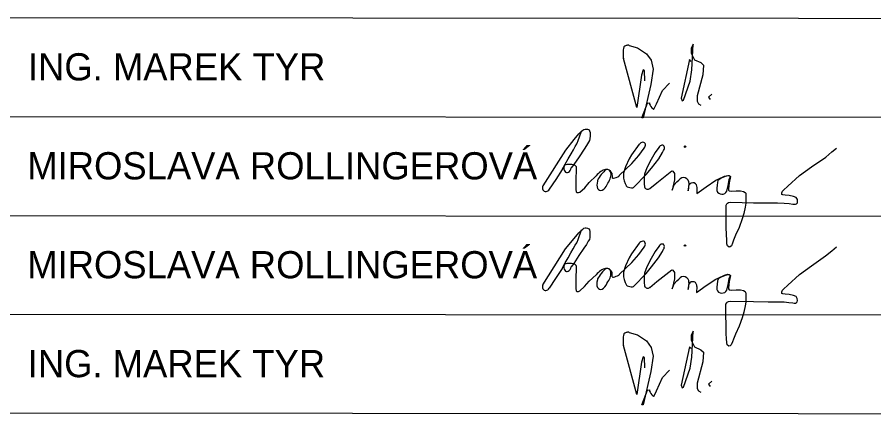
# Model space of a CAD drawing. Extents: x -467927 to -455912, y -1105662 to -1104439.
# Drawn here: x -458189.3 to -458127.1, y -1105019.6 to -1104991.1 of the extents above; entities that cross this region are included whole.
import ezdxf

# ---------------------------------------------------------------- set-up
doc = ezdxf.new("R2010")
doc.units = 0
doc.layers.add('Implicitní', color=7, linetype='Continuous')
doc.layers.add('Rozpiska TMS', color=7, linetype='Continuous')

msp = doc.modelspace()

# ---------------------------------------------------------------- linework, layer by layer
at = {"layer": 'Implicitní'}
for p, q in [((-458229.752, -1104998.32), (-458124.713, -1104998.397)), ((-458148.843, -1105000.022), (-458148.494, -1104999.613)), ((-458148.567, -1105000.17), (-458148.302, -1104999.411)), ((-458148.494, -1104999.613), (-458148.302, -1104999.418)), ((-458148.302, -1104999.418), (-458148.216, -1104999.346)), ((-458148.216, -1104999.346), (-458148.145, -1104999.292)), ((-458148.145, -1104999.292), (-458148.049, -1104999.267)), ((-458148.049, -1104999.267), (-458147.969, -1104999.267)), ((-458147.969, -1104999.267), (-458147.874, -1104999.285)), ((-458147.874, -1104999.285), (-458147.809, -1104999.308)), ((-458147.809, -1104999.308), (-458147.753, -1104999.332)), ((-458147.753, -1104999.332), (-458147.719, -1104999.406)), ((-458147.719, -1104999.406), (-458147.689, -1104999.517)), ((-458147.689, -1104999.517), (-458147.689, -1104999.755)), ((-458149.455, -1105000.795), (-458148.843, -1105000.022)), ((-458147.811, -1105000.225), (-458147.945, -1105000.46)), ((-458147.724, -1105000.094), (-458147.811, -1105000.225)), ((-458147.706, -1104999.97), (-458147.724, -1105000.094)), ((-458147.689, -1104999.755), (-458147.706, -1104999.97)), ((-458151.108, -1105003.4), (-458149.455, -1105000.795)), ((-458148.126, -1105000.735), (-458148.487, -1105001.277)), ((-458147.945, -1105000.46), (-458148.126, -1105000.735)), ((-458144.11, -1105000.376), (-458144.676, -1105001.138)), ((-458144.132, -1105001.198), (-458143.74, -1105000.665)), ((-458142.683, -1105000.613), (-458142.951, -1105000.973)), ((-458142.424, -1105000.969), (-458142.344, -1105000.817)), ((-458130.553, -1105001.306), (-458130.099, -1105000.92)), ((-458130.099, -1105000.92), (-458129.758, -1105000.648)), ((-458148.487, -1105001.277), (-458148.869, -1105001.852)), ((-458144.844, -1105001.435), (-458145.109, -1105002.013)), ((-458144.676, -1105001.138), (-458144.844, -1105001.435)), ((-458144.649, -1105001.775), (-458144.132, -1105001.198)), ((-458143.245, -1105001.485), (-458143.552, -1105002.083)), ((-458142.951, -1105000.973), (-458143.245, -1105001.485)), ((-458143.225, -1105002.104), (-458142.697, -1105001.429)), ((-458142.697, -1105001.429), (-458142.424, -1105000.969)), ((-458131.585, -1105002.01), (-458130.553, -1105001.306)), ((-458148.869, -1105001.852), (-458149.049, -1105002.086)), ((-458148.696, -1105001.998), (-458148.713, -1105003.148)), ((-458145.537, -1105002.62), (-458144.649, -1105001.775)), ((-458145.109, -1105002.013), (-458145.243, -1105002.476)), ((-458143.552, -1105002.083), (-458143.72, -1105002.551)), ((-458143.596, -1105002.581), (-458143.225, -1105002.104)), ((-458132.459, -1105002.646), (-458131.585, -1105002.01)), ((-458149.717, -1105002.221), (-458150.185, -1105002.945)), ((-458147.74, -1105003.147), (-458147.239, -1105002.677)), ((-458145.243, -1105002.476), (-458145.261, -1105002.649)), ((-458145.261, -1105002.649), (-458145.261, -1105002.834)), ((-458144.497, -1105003.49), (-458143.596, -1105002.581)), ((-458143.72, -1105002.551), (-458143.75, -1105002.738)), ((-458143.75, -1105002.738), (-458143.75, -1105003.222)), ((-458142.834, -1105003.169), (-458141.74, -1105002.303)), ((-458141.74, -1105002.303), (-458141.656, -1105002.327)), ((-458141.656, -1105002.327), (-458141.547, -1105002.496)), ((-458141.547, -1105002.496), (-458141.548, -1105002.972)), ((-458138.37, -1105002.91), (-458137.917, -1105002.7)), ((-458137.864, -1105002.722), (-458138.152, -1105002.839)), ((-458137.917, -1105002.7), (-458137.664, -1105002.638)), ((-458137.626, -1105002.673), (-458137.864, -1105002.722)), ((-458137.664, -1105002.638), (-458137.577, -1105002.643)), ((-458137.478, -1105002.722), (-458137.626, -1105002.673)), ((-458137.577, -1105002.643), (-458137.478, -1105002.722)), ((-458137.478, -1105002.722), (-458137.575, -1105003.173)), ((-458137.563, -1105002.946), (-458137.478, -1105002.722)), ((-458133.296, -1105003.421), (-458132.459, -1105002.646)), ((-458150.185, -1105002.945), (-458150.648, -1105003.642)), ((-458148.713, -1105003.148), (-458148.723, -1105003.674)), ((-458148.075, -1105003.534), (-458147.74, -1105003.147)), ((-458145.261, -1105002.834), (-458145.211, -1105003.026)), ((-458145.211, -1105003.026), (-458145.134, -1105003.239)), ((-458145.134, -1105003.239), (-458145.057, -1105003.386)), ((-458143.75, -1105003.222), (-458143.721, -1105003.49)), ((-458143.332, -1105003.588), (-458142.834, -1105003.169)), ((-458141.548, -1105002.972), (-458141.715, -1105003.705)), ((-458141.715, -1105003.705), (-458141.565, -1105003.322)), ((-458141.565, -1105003.322), (-458141.379, -1105003.105)), ((-458141.379, -1105003.105), (-458141.222, -1105002.989)), ((-458140.496, -1105003.235), (-458140.546, -1105003.755)), ((-458140.546, -1105003.755), (-458140.484, -1105003.333)), ((-458139.238, -1105003.465), (-458138.538, -1105002.981)), ((-458138.538, -1105002.981), (-458138.37, -1105002.91)), ((-458138.446, -1105003.357), (-458138.471, -1105003.569)), ((-458138.426, -1105003.145), (-458138.446, -1105003.357)), ((-458138.39, -1105003.018), (-458138.426, -1105003.145)), ((-458138.333, -1105002.954), (-458138.39, -1105003.018)), ((-458138.152, -1105002.839), (-458138.333, -1105002.954)), ((-458137.738, -1105003.784), (-458137.649, -1105003.384)), ((-458137.649, -1105003.384), (-458137.563, -1105002.946)), ((-458137.575, -1105003.173), (-458137.626, -1105003.625)), ((-458133.624, -1105003.711), (-458133.296, -1105003.421)), ((-458148.723, -1105003.674), (-458148.697, -1105003.836)), ((-458148.697, -1105003.836), (-458148.645, -1105003.892)), ((-458148.645, -1105003.892), (-458148.52, -1105003.892)), ((-458148.52, -1105003.892), (-458148.418, -1105003.85)), ((-458148.418, -1105003.85), (-458148.075, -1105003.534)), ((-458139.931, -1105003.969), (-458139.238, -1105003.465)), ((-458139.915, -1105003.527), (-458139.931, -1105003.969)), ((-458138.471, -1105003.569), (-458138.471, -1105003.744)), ((-458137.626, -1105003.625), (-458137.626, -1105003.708)), ((-458137.626, -1105003.708), (-458137.577, -1105003.765)), ((-458137.577, -1105003.765), (-458137.383, -1105003.784)), ((-458137.383, -1105003.784), (-458137.055, -1105003.768)), ((-458137.055, -1105003.768), (-458136.739, -1105003.768)), ((-458136.739, -1105003.768), (-458136.52, -1105003.812)), ((-458136.52, -1105003.812), (-458136.413, -1105003.882)), ((-458136.413, -1105003.882), (-458136.367, -1105003.933)), ((-458136.367, -1105003.933), (-458136.348, -1105004.066)), ((-458133.748, -1105003.999), (-458133.739, -1105003.919)), ((-458133.74, -1105004.033), (-458133.748, -1105003.999)), ((-458133.668, -1105004.059), (-458133.74, -1105004.033)), ((-458133.739, -1105003.919), (-458133.692, -1105003.787)), ((-458133.692, -1105003.787), (-458133.624, -1105003.711)), ((-458133.5, -1105004.077), (-458133.668, -1105004.059)), ((-458137.739, -1105004.703), (-458137.704, -1105004.668)), ((-458137.704, -1105004.668), (-458137.627, -1105004.616)), ((-458137.627, -1105004.616), (-458137.443, -1105004.59)), ((-458137.443, -1105004.59), (-458135.808, -1105004.625)), ((-458136.348, -1105004.656), (-458136.399, -1105004.943)), ((-458136.348, -1105004.066), (-458136.348, -1105004.347)), ((-458136.348, -1105004.347), (-458136.348, -1105004.656)), ((-458135.808, -1105004.625), (-458134.723, -1105004.632)), ((-458134.723, -1105004.632), (-458134.068, -1105004.632)), ((-458134.068, -1105004.632), (-458133.578, -1105004.654)), ((-458133.578, -1105004.654), (-458133.219, -1105004.68)), ((-458133.201, -1105004.111), (-458133.5, -1105004.077)), ((-458133.219, -1105004.68), (-458132.946, -1105004.726)), ((-458132.894, -1105004.183), (-458133.201, -1105004.111)), ((-458132.702, -1105004.253), (-458132.894, -1105004.183)), ((-458132.611, -1105004.391), (-458132.702, -1105004.253)), ((-458132.676, -1105004.7), (-458132.611, -1105004.633)), ((-458132.606, -1105004.536), (-458132.611, -1105004.391)), ((-458132.611, -1105004.633), (-458132.606, -1105004.536)), ((-458137.8, -1105005.494), (-458137.799, -1105004.998)), ((-458137.799, -1105004.817), (-458137.739, -1105004.703)), ((-458137.799, -1105004.998), (-458137.799, -1105004.817)), ((-458136.399, -1105004.943), (-458136.498, -1105005.406)), ((-458132.946, -1105004.726), (-458132.834, -1105004.731)), ((-458132.834, -1105004.731), (-458132.753, -1105004.731)), ((-458132.753, -1105004.731), (-458132.676, -1105004.7)), ((-458229.757, -1105005.52), (-458124.718, -1105005.597)), ((-458137.786, -1105006.436), (-458137.8, -1105005.494)), ((-458136.632, -1105005.801), (-458136.85, -1105006.42)), ((-458136.498, -1105005.406), (-458136.632, -1105005.801)), ((-458148.307, -1105006.618), (-458148.221, -1105006.546)), ((-458148.221, -1105006.546), (-458148.15, -1105006.492)), ((-458148.15, -1105006.492), (-458148.054, -1105006.467)), ((-458148.054, -1105006.467), (-458147.974, -1105006.467)), ((-458147.974, -1105006.467), (-458147.879, -1105006.485)), ((-458147.879, -1105006.485), (-458147.814, -1105006.508)), ((-458147.814, -1105006.508), (-458147.758, -1105006.532)), ((-458147.758, -1105006.532), (-458147.724, -1105006.606)), ((-458137.777, -1105006.943), (-458137.786, -1105006.436)), ((-458136.85, -1105006.42), (-458137.102, -1105007)), ((-458148.848, -1105007.222), (-458148.5, -1105006.813)), ((-458148.572, -1105007.37), (-458148.307, -1105006.611)), ((-458148.5, -1105006.813), (-458148.307, -1105006.618)), ((-458147.711, -1105007.17), (-458147.729, -1105007.294)), ((-458147.724, -1105006.606), (-458147.695, -1105006.717)), ((-458147.695, -1105006.955), (-458147.711, -1105007.17)), ((-458147.695, -1105006.717), (-458147.695, -1105006.955)), ((-458137.753, -1105007.342), (-458137.777, -1105006.943)), ((-458137.102, -1105007), (-458137.253, -1105007.352)), ((-458149.46, -1105007.995), (-458148.848, -1105007.222)), ((-458147.95, -1105007.66), (-458148.131, -1105007.935)), ((-458147.816, -1105007.425), (-458147.95, -1105007.66)), ((-458147.729, -1105007.294), (-458147.816, -1105007.425)), ((-458144.115, -1105007.576), (-458144.682, -1105008.338)), ((-458137.73, -1105007.614), (-458137.753, -1105007.342)), ((-458137.699, -1105007.768), (-458137.73, -1105007.614)), ((-458137.578, -1105007.857), (-458137.699, -1105007.768)), ((-458137.409, -1105007.768), (-458137.491, -1105007.838)), ((-458137.335, -1105007.565), (-458137.409, -1105007.768)), ((-458137.253, -1105007.352), (-458137.335, -1105007.565)), ((-458151.113, -1105010.6), (-458149.46, -1105007.995)), ((-458148.131, -1105007.935), (-458148.492, -1105008.477)), ((-458144.682, -1105008.338), (-458144.849, -1105008.635)), ((-458144.654, -1105008.975), (-458144.138, -1105008.398)), ((-458144.138, -1105008.398), (-458143.745, -1105007.865)), ((-458142.957, -1105008.173), (-458143.25, -1105008.685)), ((-458142.688, -1105007.813), (-458142.957, -1105008.173)), ((-458142.702, -1105008.629), (-458142.43, -1105008.169)), ((-458142.43, -1105008.169), (-458142.35, -1105008.017)), ((-458137.491, -1105007.838), (-458137.578, -1105007.857)), ((-458130.558, -1105008.506), (-458130.105, -1105008.12)), ((-458130.105, -1105008.12), (-458129.763, -1105007.848)), ((-458148.492, -1105008.477), (-458148.874, -1105009.052)), ((-458145.542, -1105009.82), (-458144.654, -1105008.975)), ((-458144.849, -1105008.635), (-458145.114, -1105009.213)), ((-458143.25, -1105008.685), (-458143.557, -1105009.283)), ((-458143.23, -1105009.304), (-458142.702, -1105008.629)), ((-458131.59, -1105009.21), (-458130.558, -1105008.506)), ((-458149.723, -1105009.421), (-458150.19, -1105010.145)), ((-458148.874, -1105009.052), (-458149.054, -1105009.286)), ((-458148.701, -1105009.198), (-458148.718, -1105010.348)), ((-458145.114, -1105009.213), (-458145.249, -1105009.676)), ((-458143.557, -1105009.283), (-458143.726, -1105009.751)), ((-458143.601, -1105009.781), (-458143.23, -1105009.304)), ((-458142.839, -1105010.369), (-458141.746, -1105009.503)), ((-458141.746, -1105009.503), (-458141.662, -1105009.527)), ((-458141.662, -1105009.527), (-458141.553, -1105009.696)), ((-458132.464, -1105009.846), (-458131.59, -1105009.21)), ((-458150.19, -1105010.145), (-458150.654, -1105010.842)), ((-458147.745, -1105010.347), (-458147.244, -1105009.877)), ((-458145.249, -1105009.676), (-458145.266, -1105009.849)), ((-458145.266, -1105009.849), (-458145.266, -1105010.034)), ((-458145.266, -1105010.034), (-458145.216, -1105010.226)), ((-458145.216, -1105010.226), (-458145.139, -1105010.439)), ((-458144.502, -1105010.69), (-458143.601, -1105009.781)), ((-458143.726, -1105009.751), (-458143.755, -1105009.938)), ((-458143.755, -1105009.938), (-458143.755, -1105010.422)), ((-458141.553, -1105010.172), (-458141.721, -1105010.905)), ((-458141.553, -1105009.696), (-458141.553, -1105010.172)), ((-458141.384, -1105010.305), (-458141.227, -1105010.189)), ((-458139.243, -1105010.664), (-458138.543, -1105010.181)), ((-458138.543, -1105010.181), (-458138.375, -1105010.11)), ((-458138.395, -1105010.218), (-458138.431, -1105010.345)), ((-458138.338, -1105010.154), (-458138.395, -1105010.218)), ((-458138.375, -1105010.11), (-458137.922, -1105009.9)), ((-458138.157, -1105010.039), (-458138.338, -1105010.154)), ((-458137.869, -1105009.922), (-458138.157, -1105010.039)), ((-458137.922, -1105009.9), (-458137.669, -1105009.838)), ((-458137.631, -1105009.873), (-458137.869, -1105009.922)), ((-458137.669, -1105009.838), (-458137.582, -1105009.843)), ((-458137.654, -1105010.584), (-458137.568, -1105010.146)), ((-458137.483, -1105009.922), (-458137.631, -1105009.873)), ((-458137.582, -1105009.843), (-458137.483, -1105009.922)), ((-458137.483, -1105009.922), (-458137.58, -1105010.373)), ((-458137.568, -1105010.146), (-458137.483, -1105009.922)), ((-458133.301, -1105010.621), (-458132.464, -1105009.846)), ((-458148.718, -1105010.348), (-458148.729, -1105010.874)), ((-458148.729, -1105010.874), (-458148.703, -1105011.036)), ((-458148.424, -1105011.05), (-458148.081, -1105010.734)), ((-458148.081, -1105010.734), (-458147.745, -1105010.347)), ((-458145.139, -1105010.439), (-458145.062, -1105010.586)), ((-458143.755, -1105010.422), (-458143.726, -1105010.69)), ((-458143.338, -1105010.788), (-458142.839, -1105010.369)), ((-458141.721, -1105010.905), (-458141.57, -1105010.522)), ((-458141.57, -1105010.522), (-458141.384, -1105010.305)), ((-458140.501, -1105010.435), (-458140.552, -1105010.955)), ((-458140.552, -1105010.955), (-458140.489, -1105010.533)), ((-458139.936, -1105011.169), (-458139.243, -1105010.664)), ((-458139.92, -1105010.727), (-458139.936, -1105011.169)), ((-458138.451, -1105010.557), (-458138.477, -1105010.769)), ((-458138.477, -1105010.769), (-458138.477, -1105010.944)), ((-458138.431, -1105010.345), (-458138.451, -1105010.557)), ((-458137.744, -1105010.984), (-458137.654, -1105010.584)), ((-458137.58, -1105010.373), (-458137.632, -1105010.825)), ((-458137.632, -1105010.825), (-458137.632, -1105010.908)), ((-458137.632, -1105010.908), (-458137.583, -1105010.965)), ((-458133.698, -1105010.987), (-458133.63, -1105010.911)), ((-458133.63, -1105010.911), (-458133.301, -1105010.621)), ((-458148.703, -1105011.036), (-458148.651, -1105011.092)), ((-458148.651, -1105011.092), (-458148.526, -1105011.092)), ((-458148.526, -1105011.092), (-458148.424, -1105011.05)), ((-458137.583, -1105010.965), (-458137.389, -1105010.984)), ((-458137.389, -1105010.984), (-458137.061, -1105010.968)), ((-458137.061, -1105010.968), (-458136.745, -1105010.968)), ((-458136.745, -1105010.968), (-458136.526, -1105011.012)), ((-458136.526, -1105011.012), (-458136.419, -1105011.082)), ((-458136.419, -1105011.082), (-458136.373, -1105011.133)), ((-458136.373, -1105011.133), (-458136.353, -1105011.266)), ((-458136.353, -1105011.266), (-458136.353, -1105011.547)), ((-458133.753, -1105011.199), (-458133.745, -1105011.119)), ((-458133.745, -1105011.233), (-458133.753, -1105011.199)), ((-458133.745, -1105011.119), (-458133.698, -1105010.987)), ((-458133.673, -1105011.259), (-458133.745, -1105011.233)), ((-458133.505, -1105011.277), (-458133.673, -1105011.259)), ((-458133.206, -1105011.311), (-458133.505, -1105011.277)), ((-458132.899, -1105011.383), (-458133.206, -1105011.311)), ((-458132.707, -1105011.453), (-458132.899, -1105011.383)), ((-458132.616, -1105011.591), (-458132.707, -1105011.453)), ((-458137.805, -1105012.198), (-458137.804, -1105012.017)), ((-458137.804, -1105012.017), (-458137.744, -1105011.903)), ((-458137.744, -1105011.903), (-458137.709, -1105011.868)), ((-458137.709, -1105011.868), (-458137.632, -1105011.816)), ((-458137.632, -1105011.816), (-458137.448, -1105011.79)), ((-458137.448, -1105011.79), (-458135.813, -1105011.825)), ((-458136.405, -1105012.143), (-458136.503, -1105012.606)), ((-458136.353, -1105011.856), (-458136.405, -1105012.143)), ((-458136.353, -1105011.547), (-458136.353, -1105011.856)), ((-458135.813, -1105011.825), (-458134.728, -1105011.832)), ((-458134.728, -1105011.832), (-458134.073, -1105011.832)), ((-458134.073, -1105011.832), (-458133.583, -1105011.854)), ((-458133.583, -1105011.854), (-458133.224, -1105011.88)), ((-458133.224, -1105011.88), (-458132.951, -1105011.926)), ((-458132.951, -1105011.926), (-458132.839, -1105011.931)), ((-458132.839, -1105011.931), (-458132.758, -1105011.931)), ((-458132.758, -1105011.931), (-458132.681, -1105011.9)), ((-458132.681, -1105011.9), (-458132.616, -1105011.833)), ((-458132.611, -1105011.736), (-458132.616, -1105011.591)), ((-458132.616, -1105011.833), (-458132.611, -1105011.736)), ((-458229.763, -1105012.72), (-458124.724, -1105012.797)), ((-458137.805, -1105012.694), (-458137.805, -1105012.198)), ((-458137.792, -1105013.636), (-458137.805, -1105012.694)), ((-458136.503, -1105012.606), (-458136.637, -1105013.001)), ((-458136.637, -1105013.001), (-458136.856, -1105013.62)), ((-458137.782, -1105014.143), (-458137.792, -1105013.636)), ((-458136.856, -1105013.62), (-458137.107, -1105014.2)), ((-458137.758, -1105014.542), (-458137.782, -1105014.143)), ((-458137.736, -1105014.814), (-458137.758, -1105014.542)), ((-458137.258, -1105014.552), (-458137.34, -1105014.765)), ((-458137.107, -1105014.2), (-458137.258, -1105014.552)), ((-458137.705, -1105014.968), (-458137.736, -1105014.814)), ((-458137.584, -1105015.057), (-458137.705, -1105014.968)), ((-458137.497, -1105015.038), (-458137.584, -1105015.057)), ((-458137.415, -1105014.968), (-458137.497, -1105015.038)), ((-458137.34, -1105014.765), (-458137.415, -1105014.968))]:
    msp.add_line(p, q, dxfattribs=at)
msp.add_lwpolyline([(-458229.747, -1104991.12), (-458067.742, -1104991.239), (-458067.763, -1105020.04), (-458229.768, -1105019.921)], close=True, dxfattribs=at)
for centre in [(-458140.774, -1105000.545), (-458140.78, -1105007.745)]:
    msp.add_circle(centre, 0.0535, dxfattribs=at)
for centre, radius, start, end in [((-458140.891, -1105003.204), 0.4, 355.78467, 147.22874), ((-458140.216, -1105003.485), 0.309, 352.16792, 150.33963), ((-458143.492, -1105003.412), 0.238, 197.54011, 313.10888), ((-458138.096, -1105003.616), 0.394, 199.70252, 334.88277), ((-458140.896, -1105010.404), 0.4, 355.78467, 147.22874), ((-458143.497, -1105010.612), 0.238, 197.54011, 313.10888), ((-458140.222, -1105010.685), 0.309, 352.16792, 150.33963), ((-458138.102, -1105010.816), 0.394, 199.70252, 334.88277)]:
    msp.add_arc(centre, radius, start, end, dxfattribs=at)
for centre, major_axis, ratio, start_param, end_param in [((-458149.74, -1105002.211), (1.171, 2.036), 0.009505, 4.712389, 6.283185), ((-458143.926, -1105000.52), (-0.194, -0.258), 0.719657, 1.570796, 4.712389), ((-458142.512, -1105000.715), (-0.159, -0.26), 0.66672, 1.570796, 4.712389), ((-458149.313, -1105002.027), (-0.091, -0.4), 0.65459, 4.712389, 7.853982), ((-458149.14, -1105001.985), (0.435, -0.017), 0.329233, 6.283185, 9.424778), ((-458146.847, -1105002.987), (0.566, 0.719), 0.546541, 4.712389, 7.853982), ((-458146.796, -1105002.632), (0.343, 0.419), 0.173859, 0, 3.141593), ((-458146.232, -1105002.554), (-0.221, 0.341), 0.392654, 4.712389, 6.283185), ((-458146.105, -1105002.831), (0.006, 0.363), 0.109468, 4.712389, 6.283185), ((-458145.803, -1105002.726), (0.262, 0.106), 0.227956, 3.141593, 6.283185), ((-458150.877, -1105003.52), (-0.143, -0.271), 0.856584, 4.712389, 7.853982), ((-458146.796, -1105003.174), (-0.198, -0.551), 0.62126, 4.712389, 7.853982), ((-458144.774, -1105003.441), (0.279, -0.051), 0.318058, 3.141593, 6.283185), ((-458149.745, -1105009.411), (1.171, 2.036), 0.009505, 4.712389, 6.283185), ((-458143.931, -1105007.72), (-0.194, -0.258), 0.719657, 1.570796, 4.712389), ((-458142.517, -1105007.915), (-0.159, -0.26), 0.66672, 1.570796, 4.712389), ((-458149.145, -1105009.185), (0.435, -0.017), 0.329233, 6.283185, 9.424778), ((-458149.319, -1105009.227), (-0.091, -0.4), 0.65459, 4.712389, 7.853982), ((-458146.852, -1105010.187), (0.566, 0.719), 0.546541, 4.712389, 7.853982), ((-458146.801, -1105009.832), (0.343, 0.419), 0.173859, 0, 3.141593), ((-458146.238, -1105009.754), (-0.221, 0.341), 0.392654, 4.712389, 6.283185), ((-458146.11, -1105010.031), (0.006, 0.363), 0.109468, 4.712389, 6.283185), ((-458146.802, -1105010.374), (-0.198, -0.551), 0.62126, 4.712389, 7.853982), ((-458145.808, -1105009.926), (0.262, 0.106), 0.227956, 3.141593, 6.283185), ((-458150.883, -1105010.72), (-0.143, -0.271), 0.856584, 4.712389, 7.853982), ((-458144.779, -1105010.641), (0.279, -0.051), 0.318058, 3.141593, 6.283185)]:
    msp.add_ellipse(centre, major_axis=major_axis, ratio=ratio, start_param=start_param, end_param=end_param, dxfattribs=at)
at = {"layer": 'Rozpiska TMS'}
for p, q in [((-458144.837, -1104993.183), (-458144.227, -1104993.355)), ((-458144.227, -1104993.355), (-458143.571, -1104993.793)), ((-458140.182, -1104993.089), (-458140.339, -1104993.402)), ((-458140.339, -1104993.402), (-458140.339, -1104993.746)), ((-458140.292, -1104994.965), (-458140.182, -1104993.089)), ((-458143.571, -1104993.793), (-458143.243, -1104994.261)), ((-458140.339, -1104993.746), (-458140.104, -1104994.23)), ((-458144.274, -1104997.7), (-458145.258, -1104994.121)), ((-458143.243, -1104994.261), (-458143.102, -1104994.903)), ((-458140.463, -1104994.215), (-458141.056, -1104997.012)), ((-458140.339, -1104994.34), (-458140.463, -1104994.215)), ((-458140.104, -1104994.23), (-458139.636, -1104994.434)), ((-458139.636, -1104994.434), (-458139.432, -1104994.606)), ((-458139.432, -1104994.606), (-458139.495, -1104995.309)), ((-458143.946, -1104995.34), (-458144.274, -1104997.7)), ((-458143.821, -1104994.949), (-458143.946, -1104995.34)), ((-458143.727, -1104994.996), (-458143.821, -1104994.949)), ((-458143.711, -1104995.746), (-458143.727, -1104994.996)), ((-458143.102, -1104994.903), (-458143.259, -1104996.029)), ((-458140.401, -1104995.777), (-458140.292, -1104994.965)), ((-458139.495, -1104995.309), (-458139.9, -1104996.857)), ((-458142.415, -1104996.45), (-458141.9, -1104995.919)), ((-458140.885, -1104997.153), (-458140.401, -1104995.777)), ((-458143.259, -1104996.029), (-458143.836, -1104998.451)), ((-458142.852, -1104997.435), (-458142.415, -1104996.45)), ((-458141.056, -1104997.012), (-458140.995, -1104997.216)), ((-458140.995, -1104997.216), (-458140.885, -1104997.153)), ((-458139.9, -1104996.857), (-458139.9, -1104997.247)), ((-458138.838, -1104996.716), (-458139.073, -1104996.934)), ((-458139.073, -1104996.934), (-458138.949, -1104997.106)), ((-458143.915, -1104998.451), (-458143.508, -1104997.372)), ((-458143.508, -1104997.372), (-458143.368, -1104997.357)), ((-458143.04, -1104997.825), (-458142.852, -1104997.435)), ((-458139.9, -1104997.247), (-458139.792, -1104997.435)), ((-458139.792, -1104997.435), (-458139.621, -1104997.529)), ((-458143.836, -1104998.451), (-458143.915, -1104998.451)), ((-458140.182, -1105013.985), (-458140.339, -1105014.297)), ((-458140.292, -1105015.86), (-458140.182, -1105013.985)), ((-458144.837, -1105014.078), (-458144.227, -1105014.251)), ((-458144.227, -1105014.251), (-458143.571, -1105014.689)), ((-458140.339, -1105014.297), (-458140.339, -1105014.641)), ((-458140.339, -1105014.641), (-458140.104, -1105015.125)), ((-458144.274, -1105018.595), (-458145.258, -1105015.016)), ((-458143.571, -1105014.689), (-458143.243, -1105015.157)), ((-458143.243, -1105015.157), (-458143.102, -1105015.798)), ((-458140.463, -1105015.11), (-458141.056, -1105017.908)), ((-458140.339, -1105015.235), (-458140.463, -1105015.11)), ((-458140.104, -1105015.125), (-458139.636, -1105015.329)), ((-458143.821, -1105015.845), (-458143.946, -1105016.235)), ((-458143.727, -1105015.892), (-458143.821, -1105015.845)), ((-458143.711, -1105016.642), (-458143.727, -1105015.892)), ((-458143.102, -1105015.798), (-458143.259, -1105016.924)), ((-458140.401, -1105016.672), (-458140.292, -1105015.86)), ((-458139.636, -1105015.329), (-458139.432, -1105015.501)), ((-458139.432, -1105015.501), (-458139.495, -1105016.204)), ((-458143.946, -1105016.235), (-458144.274, -1105018.595)), ((-458139.495, -1105016.204), (-458139.9, -1105017.752)), ((-458143.259, -1105016.924), (-458143.836, -1105019.346)), ((-458142.415, -1105017.346), (-458141.9, -1105016.814)), ((-458140.885, -1105018.049), (-458140.401, -1105016.672)), ((-458142.852, -1105018.33), (-458142.415, -1105017.346)), ((-458139.9, -1105017.752), (-458139.9, -1105018.143)), ((-458138.838, -1105017.611), (-458139.073, -1105017.83)), ((-458143.915, -1105019.346), (-458143.508, -1105018.267)), ((-458143.508, -1105018.267), (-458143.368, -1105018.253)), ((-458143.04, -1105018.721), (-458142.852, -1105018.33)), ((-458141.056, -1105017.908), (-458140.995, -1105018.111)), ((-458140.995, -1105018.111), (-458140.885, -1105018.049)), ((-458139.9, -1105018.143), (-458139.792, -1105018.33)), ((-458139.792, -1105018.33), (-458139.621, -1105018.424)), ((-458139.073, -1105017.83), (-458138.949, -1105018.002)), ((-458143.836, -1105019.346), (-458143.915, -1105019.346))]:
    msp.add_line(p, q, dxfattribs=at)
for centre, major_axis, ratio, start_param, end_param in [((-458145.25, -1104993.722), (0.008, 0.399), 0.064441, 0, 3.141593), ((-458145.039, -1104993.254), (0.203, 0.07), 0.314219, 0, 3.141593), ((-458143.204, -1104997.591), (0.164, -0.234), 0.219584, 3.141593, 6.283185), ((-458145.25, -1105014.618), (0.008, 0.399), 0.064441, 0, 3.141593), ((-458145.039, -1105014.149), (0.203, 0.07), 0.314219, 0, 3.141593), ((-458143.204, -1105018.486), (0.164, -0.234), 0.219584, 3.141593, 6.283185)]:
    msp.add_ellipse(centre, major_axis=major_axis, ratio=ratio, start_param=start_param, end_param=end_param, dxfattribs=at)

# ---------------------------------------------------------------- texts
at = {"layer": 'Implicitní'}
for s, p in [('ING. MAREK TYR', (-458188.558, -1104995.727)), ('MIROSLAVA ROLLINGEROVÁ', (-458188.606, -1105002.927)), ('MIROSLAVA ROLLINGEROVÁ', (-458188.611, -1105010.127)), ('ING. MAREK TYR', (-458188.574, -1105017.328))]:
    msp.add_text(s, height=1.98, rotation=359.9912, dxfattribs=at).set_placement(p)

doc.saveas('drawing.dxf')
